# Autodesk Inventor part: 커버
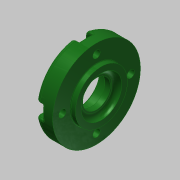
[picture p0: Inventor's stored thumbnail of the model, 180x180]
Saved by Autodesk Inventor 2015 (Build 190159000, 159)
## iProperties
Created: 2015-11
Part Number: 커버
Material: 알루미늄 6061
Document SubType Name: Modeling
Designer: mduedu
Density: 1 g/cm^3
Appearance: 매끄러움 - 짙은 산림 녹색
Author: mduedu
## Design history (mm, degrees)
sketch "스케치1"
  geometry: L1 (-7, 0)-(7, 0); L2 (-7, 0)-(-7, 27); L3 (-7, 27)-(4, 27); L4 (4, 27)-(4, 16); L5 (4, 16)-(7, 16); L6 (7, 16)-(7, 0); 2 further points
  constraints: 12 end point, 3 perpendicular, 2 parallel, 1 coincident, 1 horizontal, 1 midpoint
  dimensions: "d0" = 14 distance of L1.start L1.end; "d1" = 54 diameter of L3 L1; "d2" = 3 distance of L4.end L5.end; "d3" = 32 diameter of L5 L1
revolve "회전1" sketch "스케치1" stored, may be unused: angle "d4" = 90 deg
hole "구멍1" diameter "d7" = 25; stored, may be unused: countersink angle "d11" = 90 deg, drill point angle "d13" = 0 deg; dims "d5" = 10, "d6" = 10, "d8" = 6, "d9" = 4, "d10" = 2, "d12" = 3
hole "구멍2" diameter "d16" = 25; stored, may be unused: countersink angle "d20" = 90 deg, drill point angle "d22" = 0 deg; dims "d17" = 6, "d18" = 4, "d19" = 2, "d21" = 7.7, "d58" = 10, "d59" = 10
hole "구멍3" diameter "d25" = 17; stored, may be unused: countersink angle "d29" = 90 deg, drill point angle "d31" = 0 deg; dims "d23" = 10, "d24" = 10, "d26" = 6, "d27" = 4, "d28" = 2, "d30" = 4.2
chamfer "모따기1" distance "d32" = 0.6; stored, may be unused: second distance "d33" = 2, angle "d34" = 30 deg
fillet "모깎기1" dims "d35" = 0.3
fillet "모깎기2" dims "d36" = 3
fillet "모깎기3" dims "d37" = 3
fillet "모깎기4" dims "d38" = 0.3
sketch "스케치3" dims "d61" = 42
  geometry: C1 r 27 at (0, 0) reference; 2 further points
  constraints: 2 vertical alignment, 1 coincident, 2 other
hole "구멍4" sketch "스케치3" at (0, 21) diameter "d44" = 4.5; stored, may be unused: countersink angle "d48" = 90 deg, drill point angle "d50" = 0 deg; dims "d45" = 6, "d46" = 8, "d47" = 4.6, "d49" = 8
sketch "스케치4"
  geometry: L1 (-4, 5.702)-(-4, 0); L2 (4, 5.702)-(4, 0); A1 r 27 centre (0, -21) between (-4, 5.702) and (4, 5.702) reference; A2 r 4 centre (0, 0) between (-2.824, 2.833) and (2.824, 2.833) reference
  constraints: 4 end point, 4 point on circle, 2 tangent, 2 vertical
extrude "돌출1" cut sketch "스케치4" stored distance "d51" = 0; taper "d52" = 0 deg
fillet "모깎기5" dims "d56" = 0.3
fillet "모깎기6" dims "d57" = 1
node "솔리드1"
pattern_circular "원형 패턴2" dims angle "d64" = 360 deg
pattern_circular "원형 패턴1" dims angle "d54" = 360 deg
